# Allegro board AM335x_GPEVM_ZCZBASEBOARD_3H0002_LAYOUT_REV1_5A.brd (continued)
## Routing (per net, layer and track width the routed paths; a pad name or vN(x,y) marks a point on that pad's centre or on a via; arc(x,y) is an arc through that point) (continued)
AM335X_MCASP0_AXR0: length 145.4
  TOP w0.102: v2(81,87.4) U2.D12
  TOP w0.121: 29.5,124.75 34.58,124.75 38.91,120.43 68.04,120.43 68.36,120.75 73.13,120.75 74.92,122.55 78.23,122.55 78.53,122.85 v1(79.03,122.85) ; R451.1 87.54,155.57 86.05,154.08 85.55,154.08 85.31,153.84 84.69,153.84 84.45,154.08 81.63,154.08 81.56,154.15 v1(78.08,154.15)
  LY4 w0.133: v1(79.03,122.85) 71,114.82 71,111.47 70.01,110.48 70.01,99.61 v1(69.32,98.91)
  BOTTOM w0.102: v2(81,87.4) 81,87.6 80.58,88.02 80.58,88.4 80.36,88.62 80.04,88.62 80.04,88.62 79.92,88.62 79.79,88.75 79.79,89.19 79.6,89.38 79.03,89.38 78.94,89.47 77.05,89.47
  BOTTOM w0.121: v1(78.08,154.15) 77.53,153.61 77.53,147.97 77.33,147.76 77.33,136.97 78.03,136.27 78.03,135.03 77.91,134.92 77.91,134.1 78.97,133.04 78.97,125.25 79.26,124.96 79.26,123.56 79.61,123.21 79.61,123.2 79.64,123.17 79.65,123.17 79.92,122.9 R203.1 v1(79.03,122.85) ; 77.05,89.47 73.56,89.47 70.74,92.29 70.74,93.15 69.36,94.53 69.36,95.2 68.97,95.6 68.97,96.08 68.97,96.1 68.97,97.93 69.32,98.27 v1(69.32,98.91)
AM335X_MCASP0_AXR1: length 110.1
  TOP w0.102: v2(80.2,88.2) U2.D13
  TOP w0.121: R348.1 50.02,128.11 39.86,128.11 v1(38.52,129.45)
  LY3 w0.133: v1(33.79,87.41) 34.11,87.73 55.15,87.73 57.73,90.3 62.36,90.3 65.32,93.26 v1(70.01,93.26)
  BOTTOM w0.102: v2(80.2,88.2) 80.2,88.21 80,88.42 79.84,88.42 79.63,88.62 78.97,88.62 78.61,88.98 77.1,88.98
  BOTTOM w0.121: v1(38.52,129.45) 38.04,128.97 37.4,128.97 35.85,127.42 35.85,113.5 34.4,112.05 34.4,107.42 34.41,107.41 34.41,107.04 34.4,107.03 34.4,98.49 33.46,97.55 33.46,87.74 v1(33.79,87.41) ; v1(70.01,93.26) 70.01,93.18 69.84,93 69.84,92.48 70.18,92.14 70.19,92.14 73.35,88.98 77.1,88.98
AM335X_MCASP0_FSR: length 29.9
  TOP w0.102: v2(79.4,88.2) U2.C13
  TOP w0.121: R336.1 70.65,104.3 v1(69.44,104.3)
  BOTTOM w0.102: 77.1,88.73 77.81,88.73 78.35,88.2 v2(79.4,88.2)
  BOTTOM w0.121: v1(69.44,104.3) 69.19,104.05 69.19,100.88 68.76,100.45 68.76,99.73 68.87,99.61 68.87,98.34 68.72,98.18 68.72,96.11 68.72,96.09 68.72,95.5 68.93,95.29 68.93,95.26 69.12,95.08 69.12,94.49 68.77,94.14 68.77,92.29 69.13,91.93 70.04,91.93 70.3,91.67 70.3,91.25 71.48,90.07 71.91,90.07 73.25,88.73 77.1,88.73
AM335X_MCASP0_FSX: length 58.8
  TOP w0.102: U2.B13 78.63,88.18 77.63,88.18 77.1,88.7
  TOP w0.121: R335.1 v1(82.46,121.83) ; 77.1,88.7 76.64,89.17 75.75,89.17 74.78,90.14 69.88,90.14 v1(69.69,90.34) ; v1(67.16,117.51) 67.89,118.25 74.5,118.25 75.98,119.73 v1(81,119.73)
  BOTTOM w0.121: v1(81,119.73) 81.32,120.05 81.32,120.69 v1(82.46,121.83) R199.1 ; v1(69.69,90.34) 69.22,90.34 68.52,91.04 68.52,94.25 68.87,94.6 68.87,94.97 68.44,95.4 68.47,96.12 68.47,98.46 68.51,98.5 68.51,100.95 68.94,101.38 68.94,104.15 68.94,104.16 68.94,110.86 68.8,111 68.8,112.56 68.66,112.71 68.66,115.06 67.16,116.56 v1(67.16,117.51)
AM335X_MMC2_CLK: length 2.3
  TOP w0.121: U28.9 20.46,108.87 20,109.33 19.49,109.33 19.37,109.21 19.37,108.9 R459.1
AM335X_MMC2_CMD: length 2.3
  TOP w0.121: U28.4 22.77,111.39 22.39,111.77 22.39,112.18 R460.1
AM335X_MMC2_D0: length 126.3
  TOP w0.121: U28.6 21.77,110.89 20.42,112.24 20.42,113.95 v1(20.81,114.34)
  LY3 w0.133: v1(20.81,114.34) 21.24,114.76 24.25,114.76 24.4,114.62 25.18,114.62 25.48,114.32 34.94,114.32 39.81,119.18 51.58,119.18 53.07,120.67 68.93,120.67 69.06,120.55 69.06,119.7 69.18,119.58 70.47,119.58 70.6,119.7 70.6,120.55 70.73,120.67 71.61,120.67 71.74,120.55 71.74,119.7 71.87,119.58 73.04,119.58 73.16,119.7 73.16,120.55 73.29,120.67 74.05,120.67 75.27,121.9 81.73,121.9 82.49,121.14 105.55,121.14 105.62,121.07 105.74,121.07 v1(106.23,120.58)
  BOTTOM w0.121: R456.1 104.55,95.35 105.58,95.35 106.7,96.48 106.7,117.09 107.41,117.79 107.41,119.99 106.82,120.58 v1(106.23,120.58)
AM335X_MMC2_D1: length 126.6
  TOP w0.121: v1(20.05,114.36) 20.05,112.05 21.05,111.05 U28.7
  LY3 w0.133: v1(107.74,120.28) 107.73,120.28 106.61,121.4 83.52,121.4 82.65,122.28 74.92,122.28 74.54,121.9 70.88,121.9 70.58,121.6 70.57,121.6 70.27,121.3 68.39,121.3 68.11,121.58 67.54,121.58 66.9,120.93 52.96,120.93 51.47,119.44 39.7,119.44 34.84,114.58 25.59,114.58 25.25,114.92 24.5,114.92 24.33,115.1 20.79,115.1 v1(20.05,114.36)
  BOTTOM w0.121: v1(107.74,120.28) 107.74,117.77 106.95,116.99 106.95,96.38 105.68,95.11 103.53,95.11 R457.1
AM335X_MMC2_D2: length 126.1
  TOP w0.121: v1(25.06,114.08) 24.93,113.96 24.93,111.67 24.27,111.02 U28.1
  LY3 w0.133: v1(106.96,119.8) 106.64,120.13 105.98,120.13 105.22,120.88 87.99,120.88 87.81,120.7 82.48,120.7 81.72,121.46 75.39,121.46 73.24,119.32 63.77,119.32 63.64,119.44 63.64,119.72 63.77,119.85 68.67,119.85 68.79,119.98 68.79,120.29 68.67,120.41 53.18,120.41 51.69,118.92 39.91,118.92 34.87,113.88 25.31,113.88 25.11,114.08 v1(25.06,114.08)
  BOTTOM w0.121: v1(106.96,119.8) 107.16,119.61 107.16,117.89 106.46,117.19 106.46,97 R458.1
AM335X_MMC2_D3: length 2.2
  TOP w0.121: R491.1 23.91,112.48 23.27,111.84 U28.3
AM335X_MMC_CLK: length 64.9
  TOP w0.102: 82.65,92.9 82.65,91.35 U2.G17
  TOP w0.121: 82.65,92.9 82.65,93.59 83.16,94.1 83.16,94.12 83.21,94.16 83.21,95.53 82.82,95.92 v1(82.82,96)
  BOTTOM w0.121: v1(82.82,96) 82.82,96.31 83.22,96.71 83.22,97.24 83.22,97.45 83.07,97.6 83.07,98.2 82.89,98.38 81.73,99.54 81.73,100.81 81.4,101.14 81.4,106.03 81.39,106.04 80.76,106.67 80.76,118.49 80.75,118.49 80.75,118.7 80.76,118.76 82.01,120.02 82.01,120.49 83.56,122.04 83.56,129.67 83.43,129.79 82.81,129.79 82.69,129.91 82.69,130.15 82.81,130.27 83.43,130.27 83.56,130.39 83.56,130.63 83.43,130.75 82.81,130.75 82.69,130.88 82.69,131.12 82.81,131.24 83.43,131.24 83.56,131.36 83.56,131.6 83.43,131.72 82.81,131.72 82.69,131.84 82.69,132.08 82.81,132.2 83.43,132.2 83.56,132.32 83.56,132.56 83.43,132.69 82.81,132.69 82.69,132.81 82.69,133.05 82.81,133.17 83.43,133.17 83.56,133.29 83.56,133.53 83.43,133.65 82.81,133.65 82.69,133.77 82.69,134.01 82.81,134.13 83.43,134.13 83.56,134.25 83.56,134.5 83.43,134.62 82.81,134.62 82.69,134.74 82.69,134.98 82.81,135.1 83.43,135.1 83.56,135.22 83.56,135.47 82.71,136.31 82.71,142.66 R197.2
AM335X_MMC_CMD: length 78.7
  TOP w0.102: U2.G18 83,92.9
  TOP w0.121: v1(83.1,93.41) 83,93.31 83,92.9 ; v1(85.86,143.52) 85.42,143.52 85.27,143.67 82.52,143.67 82.39,143.55 v1(81.95,143.55)
  BOTTOM w0.121: R200.2 v1(81.95,143.55) ; v1(83.1,93.41) 83.1,93.41 83.58,93.89 83.88,93.89 85.79,95.8 85.79,102 85.6,102.19 85.6,102.56 86.38,103.34 86.39,103.34 86.39,114.46 87.03,115.11 87.03,116 87.04,116.01 87.04,116.37 87.03,116.38 87.03,122.46 88.76,124.19 88.76,126.34 88.88,126.46 90.09,126.46 90.21,126.58 90.21,126.82 90.09,126.94 88.88,126.94 88.76,127.06 88.76,127.3 88.88,127.42 90.09,127.42 90.21,127.55 90.21,127.79 90.09,127.91 88.88,127.91 88.76,128.03 88.76,128.27 88.88,128.39 90.09,128.39 90.21,128.51 90.21,128.75 90.09,128.87 88.88,128.87 88.76,128.99 88.76,129.23 88.88,129.35 90.09,129.35 90.21,129.48 90.21,129.72 90.09,129.84 88.88,129.84 88.76,129.96 88.76,130.2 88.88,130.32 90.09,130.32 90.21,130.44 90.21,130.68 90.09,130.8 88.88,130.8 88.76,130.92 88.76,131.16 88.88,131.29 90.09,131.29 90.21,131.41 90.21,131.65 90.09,131.77 88.88,131.77 88.76,131.89 88.76,132.13 88.88,132.25 90.09,132.25 90.21,132.37 90.21,132.61 90.09,132.73 88.88,132.73 87.39,134.23 87.39,140.19 85.86,141.72 v1(85.86,143.52)
AM335X_MMC_D0: length 60.5
  TOP w0.102: v2(82.6,90.6) U2.G16
  BOTTOM w0.102: 82.6,93.8 v2(82.6,90.6)
  BOTTOM w0.121: 82.6,93.8 82.05,94.34 82.05,95.92 82.97,96.84 82.97,97.34 82.83,97.49 82.83,98.1 81.48,99.44 81.48,99.64 81.48,100.71 81.15,101.04 81.15,101.62 81.15,105.92 81.14,105.94 80.5,106.58 80.5,107.03 80.5,121.14 81.77,122.41 81.77,124.85 81.51,125.12 81.51,131.66 81.63,131.78 82.26,131.78 82.38,131.9 82.38,132.14 82.26,132.26 81.63,132.26 81.51,132.38 81.51,132.63 81.63,132.75 82.26,132.75 82.38,132.87 82.38,133.11 82.26,133.23 81.63,133.23 81.26,133.6 81.26,135.22 80.24,136.24 80.24,140.69 80.36,140.81 80.36,142.83 79.77,143.42 79.18,143.42 79.15,143.45 R399.2
AM335X_MMC_D1: length 72.8
  TOP w0.102: v2(82.6,89.8) U2.G15
  TOP w0.121: v1(71.79,143.45) 72.39,142.85 80.1,142.85 80.16,142.79 80.94,142.79 82.37,141.35 83.31,141.35 83.73,141.77 84.41,141.77 84.44,141.74 v1(84.82,141.74)
  LY4 w0.133: v1(86.04,102.37) 83.63,104.79 83.63,106.26 81.76,108.13 81.76,113.91 82.16,114.31 v1(82.16,116.12)
  BOTTOM w0.102: v2(82.6,89.8) 83.02,90.22 83.02,92.59 83.32,92.9
  BOTTOM w0.121: R400.2 v1(71.79,143.45) ; v1(82.16,116.12) 82.16,117.74 83.58,119.16 83.58,120.81 84.75,121.98 84.75,123.56 85.95,124.76 85.95,128.75 84.93,129.78 84.93,140.11 84.82,140.21 v1(84.82,141.74) ; v1(86.04,102.37) 86.04,95.54 84.34,93.84 84.26,93.84 83.32,92.9
AM335X_MMC_D2: length 89.5
  TOP w0.102: 82.4,93.1 82.4,92 U2.F18
  TOP w0.121: v1(69.23,143.45) 67.14,143.45 67.02,143.32 67.02,142.53 67.14,142.4 67.23,142.4 67.35,142.28 67.35,141.64 67.47,141.52 67.71,141.52 67.83,141.64 67.83,142.28 67.95,142.4 68.19,142.4 68.32,142.28 68.32,141.64 68.44,141.52 68.68,141.52 68.8,141.64 68.8,142.28 68.92,142.4 69.16,142.4 69.28,142.28 69.28,141.64 69.4,141.52 69.64,141.52 69.76,141.64 69.76,142.28 69.88,142.4 70.37,142.4 70.49,142.28 70.49,141.57 70.61,141.45 70.85,141.45 70.97,141.57 70.97,142.28 71.1,142.4 71.34,142.4 71.46,142.28 71.46,141.57 71.58,141.45 71.82,141.45 71.94,141.57 71.94,142.28 72.06,142.4 72.3,142.4 72.42,142.28 72.42,141.57 72.54,141.45 72.78,141.45 72.9,141.57 72.9,142.28 73.03,142.4 73.27,142.4 73.39,142.28 73.39,141.57 73.51,141.45 73.75,141.45 73.87,141.57 73.87,142.28 73.99,142.4 74.23,142.4 74.35,142.28 74.35,141.57 74.47,141.45 74.71,141.45 74.84,141.57 74.84,142.28 74.96,142.4 75.2,142.4 75.32,142.28 75.32,141.57 75.44,141.45 75.68,141.45 75.8,141.57 75.8,142.28 75.92,142.4 76.16,142.4 76.28,142.28 76.28,141.57 76.4,141.45 76.65,141.45 76.77,141.57 76.77,142.28 76.89,142.4 77.13,142.4 77.25,142.28 77.25,141.57 77.37,141.45 77.61,141.45 77.73,141.57 77.73,142.28 77.85,142.4 78.09,142.4 78.21,142.28 78.21,141.57 78.33,141.45 78.58,141.45 78.7,141.57 78.7,142.28 78.82,142.4 v1(79.92,142.4) ; 82.4,93.1 82.4,94.66 82.33,94.74 82.33,96.38 82.42,96.47 v1(82.42,97.09)
  BOTTOM w0.121: v1(82.42,97.09) 81.44,98.06 81.44,98.71 80.87,99.28 80.87,100.62 80.64,100.85 80.64,105.73 80.01,106.37 80.01,106.83 80.01,107.3 79.38,107.93 79.38,120.78 80.56,121.96 80.56,124.75 81.02,125.21 81.02,129.75 80.37,130.4 80.37,134.77 v1(80.31,134.83) 80.31,135.28 79.67,135.92 79.67,141.25 79.41,141.51 79.41,141.9 v1(79.92,142.4) ; R215.2 v1(69.23,143.45)
AM335X_MMC_D3: length 86.9
  TOP w0.102: 81.89,91.97 81.89,91.96 81.87,91.94 81.87,91.31 82.18,91 U2.F17
  TOP w0.121: v1(82.38,97.79) 82.18,97.59 82.18,97.48 81.97,97.27 81.97,94.74 82.16,94.56 82.16,92.24 81.89,91.97 ; v1(79.92,141.62) 79.83,141.62 79.41,141.2 79.13,141.2 79.01,141.08 79.01,140.93 78.89,140.81 78.65,140.81 78.53,140.93 78.53,141.08 78.41,141.2 78.16,141.2 78.04,141.08 78.04,140.93 77.92,140.81 77.68,140.81 77.56,140.93 77.56,141.08 77.44,141.2 77.2,141.2 77.08,141.08 77.08,140.93 76.96,140.81 76.72,140.81 76.6,140.93 76.6,141.08 76.48,141.2 76.23,141.2 76.11,141.08 76.11,140.93 75.99,140.81 75.75,140.81 75.63,140.93 75.63,141.08 75.51,141.2 75.27,141.2 75.15,141.08 75.15,140.93 75.03,140.81 74.79,140.81 74.67,140.93 74.67,141.08 74.55,141.2 74.3,141.2 74.18,141.08 74.18,140.93 74.06,140.81 73.82,140.81 73.7,140.93 73.7,141.08 73.58,141.2 73.34,141.2 73.22,141.08 73.22,140.93 73.1,140.81 72.86,140.81 72.74,140.93 72.74,141.08 72.61,141.2 72.37,141.2 72.25,141.08 72.25,140.93 72.13,140.81 71.89,140.81 71.77,140.93 71.77,141.08 71.65,141.2 71.41,141.2 71.29,141.08 71.29,140.93 71.17,140.81 70.93,140.81 70.81,140.93 70.81,141.08 70.68,141.2 70.44,141.2 70.32,141.08 70.32,140.93 70.2,140.81 69.96,140.81 69.84,140.93 69.84,141.08 69.72,141.2 69.48,141.2 69.36,141.08 69.36,140.93 69.24,140.81 69,140.81 68.87,140.93 68.87,141.08 68.75,141.2 67.05,141.2 66.36,141.9 v1(66.36,142.94)
  BOTTOM w0.121: v1(82.38,97.79) 81.88,98.3 81.88,98.66 81.24,99.3 81.24,99.34 81.24,100.6 81.12,100.72 80.89,100.95 80.89,105.84 80.25,106.47 80.25,106.93 80.25,107.4 79.63,108.03 79.63,109.06 79.75,109.18 80.13,109.18 80.25,109.3 80.25,109.54 80.13,109.66 79.75,109.66 79.63,109.78 79.63,110.03 79.75,110.15 80.13,110.15 80.25,110.27 80.25,110.51 80.13,110.63 79.75,110.63 79.63,110.75 79.63,110.99 79.75,111.11 80.13,111.11 80.25,111.23 80.25,111.47 80.13,111.59 79.75,111.59 79.63,111.71 79.63,111.96 79.75,112.08 80.13,112.08 80.25,112.2 80.25,112.44 80.13,112.56 79.75,112.56 79.63,112.68 79.63,112.92 79.75,113.04 80.13,113.04 80.25,113.16 80.25,113.4 80.13,113.52 79.75,113.52 79.63,113.64 79.63,113.89 79.75,114.01 80.13,114.01 80.25,114.13 80.25,114.37 80.13,114.49 79.75,114.49 79.63,114.61 79.63,114.85 79.75,114.97 80.13,114.97 80.25,115.09 80.25,115.33 80.13,115.45 79.75,115.45 79.63,115.58 79.63,115.82 79.75,115.94 80.13,115.94 80.25,116.06 80.25,116.3 80.13,116.42 79.75,116.42 79.63,116.54 79.63,116.78 79.75,116.9 80.13,116.9 80.25,117.02 80.25,117.26 80.13,117.39 79.75,117.39 79.63,117.51 79.63,117.75 79.75,117.87 80.13,117.87 80.25,117.99 80.25,118.23 80.13,118.35 79.75,118.35 79.63,118.47 79.63,118.71 79.75,118.83 80.13,118.83 80.25,118.95 80.25,119.19 80.13,119.32 79.75,119.32 79.63,119.44 79.63,119.68 79.75,119.8 80.13,119.8 80.25,119.92 80.25,120.16 80.13,120.28 79.75,120.28 79.63,120.4 79.63,120.65 81.26,122.28 81.26,130.02 80.62,130.67 80.62,134.45 80.81,134.65 80.81,135.16 79.99,135.98 79.99,141.55 v1(79.92,141.62) ; v1(66.36,142.94) 66.36,143.29 66.46,143.39 R396.2
AM335X_OSC0_IN: length 20.2
  TOP w0.102: 94.38,85.1 92.78,85.1 92.47,85.4 U2.V10
  TOP w0.121: Y2.3 106.97,78.65 106.97,79.92 106.74,80.15 C4.1 101.41,80.76 101.41,80.94 R7.2 99.85,82.49 99.85,84.18 98.45,85.58 94.86,85.58 94.38,85.1
AM335X_OSC0_OUT: length 11.4
  TOP w0.121: U2.U11 91.43,86.63 91.91,86.63 92.04,86.76 92.95,86.76 93.37,87.17 94.36,87.17 95.32,86.21 98.78,86.21 100.06,84.93 100.52,84.93 R8.1
AM335X_OSC1_IN: length 15.2
  TOP w0.102: 77.74,81.97 77.97,81.97 U2.A6
  TOP w0.121: Y1.4 64.93,79.11 65.71,79.9 65.86,79.9 66.71,80.74 C2.2 67.42,80.77 67.45,80.8 68.46,80.8 68.83,80.43 71.12,80.43 71.35,80.66 72.66,80.66 73.32,81.32 75.69,81.32 76.01,81.64 76.42,81.64 76.43,81.63 77.2,81.63 77.22,81.6 77.36,81.6 77.74,81.97
AM335X_OSC1_OUT: length 8.5
  TOP w0.102: 77.1,80.89 77.91,80.89 U2.A4
  TOP w0.121: 77.1,80.89 76.32,80.89 75.34,79.91 71.66,79.91 71.27,79.53 70.95,79.53 70.84,79.41 R5.1
AM335X_PORZ: length 31.8
  TOP w0.102: U2.B15 79,89.41 78.54,89.87 78.06,89.87
  TOP w0.121: 78.06,89.87 77.33,89.87 76.99,90.22 76.67,90.22 v1(76.36,90.53) ; v1(70.62,100.19) 70.62,99.58 70.52,99.48 R9.2 69.69,99.8 69.69,100.05 69.69,100.05 69.69,100.1 69.4,100.39 68.57,100.39 67.36,99.19 65.02,99.19 64.16,98.34 63.76,98.34 63.28,98.82 61.96,98.82 v1(61.81,98.97)
  LY4 w0.133: v1(61.81,98.97) 62.13,99.29 62.29,99.29 63.16,100.16 63.16,101.12 62.78,101.51 v1(62.78,102.07)
  BOTTOM w0.121: v1(70.62,100.19) 71.14,100.19 71.47,99.86 71.47,98.59 71.86,98.21 72.55,98.21 73.19,97.57 73.19,94.22 74.33,93.08 74.33,92.37 75.73,90.97 75.92,90.97 v1(76.36,90.53) ; R2.1 v1(62.78,102.07)
AM335X_RTC_PORZ: length 50
  TOP w0.102: 76.32,81.39 77.49,81.39 77.86,81.76 78.65,81.76 79,81.41 U2.B5
  TOP w0.121: 76.32,81.39 76.12,81.39 75.79,81.06 73.44,81.06 72.79,80.41 71.45,80.41 71.22,80.17 68.73,80.17 68.55,80.36 v1(68.11,80.36) ; U1.4 53.7,103.05 53.5,102.85 53.5,99.88 54.06,99.33 56.43,99.33 57.11,98.64 v1(59.6,98.64)
  LY3 w0.133: v1(61.93,80.68) 61.93,80.64 62.21,80.36 v1(68.11,80.36)
  BOTTOM w0.121: v1(61.93,80.68) 61.71,80.9 61.71,82.64 61.08,83.28 61.08,86.18 60.79,86.47 60.36,86.91 60.36,87.52 60.36,87.52 60.36,87.91 59.22,89.05 59.22,92.18 59.3,92.27 59.3,93.56 59.3,93.56 59.3,94.48 60.08,95.26 60.08,98.16 v1(59.6,98.64) 60.54,99.58 60.77,99.58 R4.2
AM335X_SPI0_CS0: length 107
  TOP w0.102: v2(77.3,90.46) 77.48,90.28 78.12,90.28 U2.A16
  TOP w0.121: R313.2 131.36,95.29 v1(131.86,95.8)
  LY3 w0.133: v1(119.82,108.7) 119.52,109 119.52,109.97 119.1,110.39 118.72,110.39 118.63,110.3 108.98,110.3 108.04,111.24 101.08,111.24 100.27,112.04 90.57,112.04 89.6,113.01 87.59,113.01 87.34,113.26 86.97,113.26 86.68,112.97 77.84,112.97 77.3,112.43 v1(69.86,112.43)
  BOTTOM w0.102: 77.1,90.44 77.13,90.46 v2(77.3,90.46)
  BOTTOM w0.121: v1(119.82,108.7) 120.36,108.7 120.63,108.43 120.63,97.56 122.83,95.36 130.41,95.36 130.85,95.8 v1(131.86,95.8) ; 77.1,90.44 76.75,90.08 75.73,90.08 73.83,91.98 73.83,92.82 72.69,93.96 72.69,94 72.68,94.02 72.68,95.67 R552.1 72.94,96.94 72.94,97.48 72.51,97.91 71.81,97.91 71.09,98.62 71.09,99.42 70.76,99.75 70.44,99.75 70.18,100.01 70.18,100.6 70.01,100.77 70.01,103.48 70.38,103.85 70.38,105.79 69.69,106.48 69.69,111.31 69.86,111.49 v1(69.86,112.43)
AM335X_SPI0_CS1: length 10.4
  TOP w0.102: v2(79.4,89.8) U2.C15
  TOP w0.121: v1(73.01,90.83) 73.02,90.84 73.02,91.16 72.61,91.56 72.61,91.82 72.3,92.13 R380.2 72.29,92.19 71.33,92.19 R208.1
  BOTTOM w0.102: v2(79.4,89.8) 79.32,89.72 77.1,89.72
  BOTTOM w0.121: v1(73.01,90.83) 73.01,90.44 73.73,89.72 77.1,89.72
AM335X_SPI0_D0: length 106.7
  TOP w0.102: U2.B17 78.65,91.35 77.1,91.35
  TOP w0.121: v1(74.36,133.26) 74.79,133.26 74.92,133.39 74.92,133.64 75.04,133.77 76.36,133.77 76.48,133.65 76.48,132.9 76.6,132.78 76.84,132.78 76.96,132.9 76.96,133.65 77.08,133.77 77.33,133.77 77.45,133.65 77.45,132.9 77.57,132.78 77.81,132.78 77.93,132.9 77.93,133.65 78.05,133.77 79.09,133.77 79.22,133.64 79.22,132.56 79.09,132.43 74.27,132.43 74.08,132.24 74.08,132.05 74.27,131.86 80.02,131.86 81.39,133.23 81.39,133.51 81.26,133.64 79.79,133.64 79.67,133.77 R436.1 ; 77.1,91.35 76.82,91.63 75.01,91.63 74.33,92.3 74.33,94.69 v1(73.88,95.13)
  BOTTOM w0.121: v1(73.88,95.13) 73.88,96.93 74.52,97.57 74.52,97.84 76.1,99.42 76.1,103.29 75.98,103.42 75.98,106.8 76.1,106.92 77.07,106.92 77.19,107.04 77.19,107.28 77.07,107.41 76.1,107.41 75.98,107.53 75.98,107.77 76.1,107.89 77.07,107.89 77.19,108.01 77.19,108.25 77.07,108.37 76.1,108.37 75.98,108.49 75.98,108.93 76.1,109.05 76.97,109.05 77.09,109.17 77.09,109.41 76.97,109.53 76.1,109.53 75.98,109.65 75.98,109.9 76.1,110.02 76.97,110.02 77.09,110.14 77.09,110.38 76.97,110.5 76.1,110.5 75.98,110.62 75.98,110.86 76.1,110.98 76.97,110.98 77.09,111.1 77.09,111.34 76.97,111.46 76.1,111.46 75.98,111.58 75.98,111.83 76.1,111.95 76.97,111.95 77.09,112.07 77.09,112.31 76.97,112.43 76.1,112.43 75.98,112.55 75.98,112.79 76.1,112.91 76.97,112.91 77.09,113.03 77.09,113.27 76.97,113.39 76.1,113.39 75.98,113.52 75.98,113.76 76.1,113.88 76.97,113.88 77.09,114 77.09,114.24 76.97,114.36 76.1,114.36 75.98,114.48 75.98,114.72 76.1,114.84 76.97,114.84 77.09,114.96 77.09,115.2 76.97,115.32 76.1,115.32 75.98,115.45 75.98,115.69 76.1,115.81 76.97,115.81 77.09,115.93 77.09,116.17 76.97,116.29 76.1,116.29 75.98,116.41 75.98,116.65 76.1,116.77 76.97,116.77 77.09,116.89 77.09,117.13 76.97,117.26 76.1,117.26 75.98,117.38 75.98,118.23 76.1,118.35 76.75,118.35 76.87,118.47 76.87,118.71 76.75,118.83 76.1,118.83 75.98,118.95 75.98,119.84 75.29,120.53 75.29,120.63 73.5,122.42 73.5,129.65 73.37,129.77 72.68,129.77 72.55,129.9 72.55,130.55 72.68,130.67 74.6,130.67 74.72,130.79 74.72,131.04 74.6,131.16 71.89,131.16 71.77,131.28 71.77,131.51 71.89,131.64 74.6,131.64 74.72,131.76 74.72,132 74.6,132.12 73.93,132.12 73.81,132.24 73.81,132.71 v1(74.36,133.26)
AM335X_SPI0_D1: length 15
  TOP w0.102: U2.B16 78.61,90.59 78.1,90.59 77.83,90.85
  TOP w0.121: R177.1 71.54,93.76 71.99,93.32 72.37,93.32 v1(72.81,92.87) 73.06,92.62 73.32,92.62 74.8,91.13 76.62,91.13 76.89,90.85 77.83,90.85
  BOTTOM w0.121: v1(72.81,92.87) 71.72,93.96 71.72,95.34 71.03,96.03 R553.1
AM335X_SPI0_SCLK: length 8
  TOP w0.102: 78.02,91 U2.A17
  TOP w0.121: 78.02,91 77.92,91.1 77,91.1 76.72,91.38 74.9,91.38 73.25,93.04 73.25,93.06 72.99,93.32 72.97,93.32 72.66,93.63 72.19,93.63 72.07,93.75 72.06,93.75 R201.1
AM335X_UART0_CTSN: length 13.6
  TOP w0.102: 81.91,92.9 81.91,92.31 U2.E18
  TOP w0.121: 81.91,92.9 81.91,94.45 81.73,94.64 81.73,97.48 81.94,97.7 81.94,99.74 79.29,102.4 79.29,103.16 R61.2
AM335X_UART0_RTSN: length 10.8
  TOP w0.102: U2.E17 81.4,91.01 81.06,91.35 81.06,91.99 81.65,92.57 81.65,92.9
  TOP w0.121: R362.2 80.17,99.23 81.34,99.23 81.69,98.87 81.69,97.87 81.66,97.83 81.66,97.83 81.48,97.65 81.48,97.48 81.48,94.53 81.65,94.36 81.65,92.9
AM335X_UART0_RXD: length 105
  TOP w0.102: v2(81,89.8) U2.E15
  TOP w0.121: v1(52.23,63.41) R249.2 ; v1(78.64,105.46) 78.02,104.84 77.81,104.84 77.4,104.44 77.4,103.47 78.4,102.48 78.4,100.2 78.15,99.95 78.15,99.52 78.57,99.1 79.54,99.1 80.17,98.46 R363.2 80.2,98.08 80.62,97.66 80.91,97.66 81.23,97.34 81.23,97.17 81.23,94.53 81.18,94.48 v1(81.18,94.04)
  LY3 w0.133: v1(51.14,107.12) 51.48,107.46 51.48,107.59 51.74,107.85 51.87,107.85 51.9,107.89 53.17,107.89 54.52,106.54 77.56,106.54 v1(78.64,105.46)
  BOTTOM w0.102: v2(81,89.8) 81,89.83 80.58,90.24 80.58,90.97
  BOTTOM w0.121: v1(51.14,107.12) 47.43,107.12 44.84,104.53 44.84,103.38 44.81,103.35 44.81,98.78 44.64,98.61 44.64,94.02 45.12,93.53 45.12,80.81 44.35,80.04 43.04,78.72 43.04,71.95 48.02,66.97 51.22,66.97 52.23,65.95 v1(52.23,63.41) ; 80.58,90.97 80.54,91.01 80.54,93.45 81.14,94.04 v1(81.18,94.04)
AM335X_UART0_TXD: length 15.9
  TOP w0.102: v2(81,90.6) U2.E16
  TOP w0.121: v1(79,96.27) 78.7,96.57 73.31,96.57 R361.2
  BOTTOM w0.102: 80.79,92.9 80.79,92.36 81,92.15 v2(81,90.6)
  BOTTOM w0.121: v1(79,96.27) 79.05,96.33 80.76,96.33 81.62,95.46 81.62,93.79 81.42,93.59 81.06,93.59 80.79,93.31 80.79,92.9
AM335X_UART1_CTSN: length 17.9
  TOP w0.102: U2.D18 80.74,91.94
  TOP w0.121: R357.1 75.86,103.54 76.56,103.54 v1(76.56,103.54) ; 80.74,91.94 80.74,94.51 80.98,94.75 80.98,96.53 80.79,96.73 v1(80.79,96.99)
  BOTTOM w0.121: v1(76.56,103.54) 78.12,103.54 79.46,102.2 79.46,101.15 78.93,100.62 78.9,100.62 79.45,100.08 79.45,96.83 79.71,96.57 80.37,96.57 80.78,96.99 v1(80.79,96.99)
AM335X_UART1_RTSN: length 17.7
  TOP w0.102: 80.24,91.92 80.24,91.35 80.59,91 U2.D17
  TOP w0.121: 80.24,91.92 80.49,92.17 80.49,94.69 80.74,94.93 80.74,96.41 80.34,96.81 80.34,97.3 80.14,97.51 77.57,97.51 76.74,98.34 76.74,99.99 R443.1 76.75,101 76.75,102.17 v1(76.54,102.37)
  BOTTOM w0.121: v1(76.54,102.37) 76.54,102.35 76.9,101.99 76.9,101.33 77.61,100.62 77.76,100.62
AM335X_UART1_RXD: length 15.5
  TOP w0.102: v2(80.2,90.6) U2.D16
  TOP w0.121: v1(79.88,95.88) 79.88,96.39 79.01,97.26 77.47,97.26 76.36,98.37 76.36,98.59 75.48,99.48 74.59,99.48 74.34,99.23 73.19,99.23 R356.1
  BOTTOM w0.102: 80.29,93.51 80.29,91.06 80.2,90.97 v2(80.2,90.6)
  BOTTOM w0.121: v1(79.88,95.88) 80.29,95.47 80.29,93.51
AM335X_UART1_TXD: length 12.7
  TOP w0.102: v2(80.2,89.8) U2.D15
  TOP w0.121: R91.2 75.34,96.81 79.11,96.81 79.44,96.48 79.44,95.7 79.85,95.29 v1(79.85,95.16)
  BOTTOM w0.102: v2(80.2,89.8) 79.98,90.02 79.98,90.04 79.78,90.25 79.78,90.43
  BOTTOM w0.121: 79.78,90.43 79.79,90.44 79.79,90.84 79.99,91.04 79.99,91.06 80.05,91.12 80.05,94.49 79.85,94.68 v1(79.85,95.16)
AM335X_USB0_CE: length 14.1
  TOP w0.102: v2(87.4,89.8) U2.M15
  TOP w0.121: v1(93.67,99.26) 93.64,99.23 93.64,99.09 93.14,98.59 TP23.1
  LY3 w0.133: v1(93.67,99.26) 93.25,98.84 92.24,98.84 89.57,96.18 89.57,95.13 87.86,93.42 87.86,90.82 87.8,90.76 87.8,90.46 87.8,90.46 87.8,90.21 87.4,89.81 v2(87.4,89.8)
AM335X_USB0_DRVVBUS: length 106.2
  TOP w0.102: U2.F16 v2(81.8,90.6)
  TOP w0.121: v1(138.42,144.6) 137.87,145.15 U22.4
  LY3 w0.133: v1(138.42,144.6) 137.36,143.55 121.45,143.55 118.66,140.75 101.51,140.75 94.59,133.83 v1(86.4,133.83)
  LY4 w0.133: v2(81.8,90.6) 81.8,91.45 80.97,92.29 80.96,92.29 80.73,92.52 80.73,92.52 80.49,92.77 80.49,94.33 81.33,95.18 81.33,97.27 81.26,97.34 81.26,98.24 81.33,98.31 81.33,117.58 82.49,118.73 83.07,118.73 83.98,119.65 83.98,129.51 85.06,130.59 85.06,132.69 86.21,133.83 v1(86.4,133.83)
  BOTTOM w0.121: v1(138.42,144.6) 137.35,144.6 R383.1
AM335X_USB0_VBUS: length 17.6
  TOP w0.254: v2(89,89.8) U2.P15 ; R563.2 96.3,96.24 D9.1
  TOP w0.508: v1(94.84,97.05) 95.99,97.05 R563.2
  LY3 w0.127: 89.01,91.27 89.41,90.88 89.41,90.21 v2(89,89.8)
  LY3 w0.133: 89.01,91.27 88.6,90.86 88.6,90.2 v2(89,89.8)
  LY3 w0.508: 89.01,91.27 89.01,93.79 90,94.78 90.64,94.78 91.99,96.13 91.99,97.01 92.47,97.5 94.39,97.5 v1(94.84,97.05)
AM335X_USB1_CE: length 6.2
  TOP w0.102: 88.6,92.9 U2.P18
  TOP w0.121: 88.6,92.9 88.6,93.55 89.56,94.52 90.45,94.52 91.35,95.41 TP36.1
AM335X_USB1_DRVVBUS: length 133.6
  TOP w0.102: U2.F15 v2(81.8,89.8)
  TOP w0.121: U29.4 v1(146.58,144.83)
  LY3 w0.133: v1(143.36,132.94) 142.53,133.77 142.53,139.48 138.85,143.17 121.7,143.17 118.91,140.37 101.76,140.37 94.65,133.26 86.21,133.26 v1(85.57,133.9)
  LY4 w0.133: v1(85.57,133.9) 83.54,131.86 83.54,121.57 82.49,120.53 82.49,119.49 80.56,117.55 80.56,105.07 79.98,104.5 79.98,98.78 80.34,98.43 80.34,94.88 79.98,94.53 79.98,92.9 81.41,91.48 81.41,90.77 81.4,90.76 81.4,90.2 v2(81.8,89.8)
  BOTTOM w0.121: R387.1 146.21,145.2 v1(146.58,144.83) 146.58,143.09 146.34,142.85 145.33,142.85 145.01,142.53 145.01,137.51 143.42,135.93 143.42,133.01 v1(143.36,132.94)
AM335X_USB1_VBUS: length 13.7
  TOP w0.254: U2.T18 v2(90.2,92.37) ; D10.1 90.4,101.19 v1(89.85,101.74)
  TOP w0.508: R564.2 90.28,102.95 90.08,102.75 90.08,101.97 v1(89.85,101.74)
  LY4 w0.508: v2(90.2,92.37) 90.51,92.37 91.27,93.13 91.27,95.87 90.66,96.48 90.66,100.93 v1(89.85,101.74)
AM335X_VDDA_ADC: length 42.7
  TOP w0.381: v2(80.2,83.4) U2.D8
  TOP w0.508: v1(76.82,82.08) 76.64,82.08 76.58,82.14 73.32,82.14 72.27,81.1 71.02,81.1 70.79,80.87 70.26,80.87 70.26,80.87 70.21,80.87 69.29,81.79 66.12,81.79 66.03,81.7 65.8,81.46 64.49,81.46 64.38,81.57 60.28,81.57 60.17,81.68 v1(59.54,81.68) ; v1(49.31,74.43) v1(59,74.43)
  BOTTOM w0.152: v1(76.82,82.08) 77.19,82.08 77.82,82.71 79.67,82.71 80.2,83.25 v2(80.2,83.4)
  BOTTOM w0.508: R501.1 v1(49.31,74.43) 49.6,74.71 50.33,74.71 ; v1(59,74.43) 59.54,74.97 59.54,79.68 59.52,79.7 59.52,81.66 v1(59.54,81.68)
AM335X_VDDS: length 40.2
  TOP w0.305: v2(81,81.8) U2.E6
  TOP w0.381: v2(89,89) U2.P14 ; v2(85.8,88.2) U2.K13 ; v2(88.2,81.8) U2.N6 ; v2(82.6,84.2) U2.F9 ; v2(89,84.2) U2.P9 ; U2.E14 v2(81,89)
  TOP w0.635: v1(99.99,111.54) 99.1,111.54 97.69,110.14 94.44,110.14 93.18,108.88 v1(88.21,108.88)
  LY4 w0.635: v1(88.21,108.88) 88.21,99.66 87.83,99.29 v1(87.83,98.59)
  BOTTOM w0.102: 81.42,90.21 81.42,89.68 81,89.26 v2(81,89) ; 81.42,90.21 81.42,91.07 C96.1 82.21,91.1 82.21,90.33 82.08,90.21 81.42,90.21
  BOTTOM w0.508: C50.1 92.43,89.68 92.71,89.95 92.77,89.95 v1(92.9,90.08) 92.45,90.52 C48.1
  BOTTOM w0.635: C249.1 99.99,110.43 v1(99.99,111.54) 100.37,111.92 100.37,112.56 C89.1 100.75,115.32 R498.1
AM335X_VDDS_DDR: length 65.6
  TOP w0.381: U2.F5 v2(81.8,81) U2.E5 ; U2.H5 v2(84.2,81) U2.J5 ; v2(82.6,81) U2.G5 ; U2.L5 v2(85.8,81) U2.K5
  TOP w0.635: R508.2 115.7,69.44 116.29,68.85 116.29,65.75 115.6,65.06 110.9,65.06 108.24,67.71 C233.1 105.36,67.71 104.37,68.7 104.37,70.33 101.57,73.13 v1(97.62,73.13) v1(97.04,73.13) v1(96.43,73.13)
  LY3 w0.635: v1(97.62,73.13) v1(97.04,73.13) v1(96.43,73.13) 95.3,74.26 v1(86.14,74.26)
  LY4 w0.635: 92.34,82.38 92.65,82.08 93.54,82.08 94.02,81.6 94.02,80.56 94.53,80.05 94.53,77.76 96.43,75.86 v1(96.43,73.13) v1(97.04,73.13) v1(97.62,73.13)
  BOTTOM w0.381: C76.1 83.3,81.7 v2(82.6,81) ; C309.1 85.69,73.8 v1(86.14,74.26) ; v2(85.8,81) 85.86,80.94 C78.1 ; v1(96.43,73.13) 96.31,73 95.61,73 C80.1 ; v2(84.2,81) 84.26,80.94 C79.1 ; C77.1 81.76,81.04 v2(81.8,81) ; C82.1 v1(97.62,73.13)
  BOTTOM w0.635: v1(97.62,73.13) v1(97.04,73.13) v1(96.43,73.13)
AM335X_VDDSHV1: length 54
  TOP w0.381: U2.P8 v2(89,83.4) U2.P7
  LY3 w0.102: 91.74,82.52 91.43,82.21 89.45,82.21 89,82.65 v2(89,83.4) 89.26,83.4 89.64,83.02 89.65,83.02 89.69,82.98 91.29,82.98
  LY3 w0.508: 91.29,82.98 92.06,82.21 95.67,82.21 98.34,79.54 99.16,79.54 99.8,80.17 v1(99.99,80.17) 100.62,80.81 100.62,81.95 101.38,82.71 v1(102.91,82.71) 103.54,83.35 107.1,83.35 v1(108.37,82.08)
  BOTTOM w0.381: v2(89,83.4) 88.31,83.4 C31.1
  BOTTOM w0.508: v1(102.91,82.71) 103.8,82.71 C32.1 ; C258.1 101.65,79.4 101.38,79.67 100.49,79.67 v1(99.99,80.17) ; v1(108.37,82.08) 115.48,74.97 120.69,74.97 122.11,73.54 R493.1
AM335X_VDDSHV2: length 39.3
  TOP w0.381: U2.P10 88.6,85.46 88.72,85.58 88.72,86.02 88.6,86.14 U2.P11 v2(89,86.6)
  TOP w0.508: C259.1 97.89,86.7 v1(95.85,86.7) 95.85,87.59 C92.1
  LY3 w0.635: v1(115.42,95.03) 110.5,95.03 108.29,92.82 102.4,92.82 101.12,91.54 101.12,89.74 99.11,87.73 96.87,87.73 v1(95.85,86.7) 95.07,86.7 94.73,87.04 93.69,87.04 93,86.35 92.54,86.35 91.99,85.8 89.68,85.8 89.15,86.33 89.15,86.45 v2(89,86.6)
  BOTTOM w0.381: v2(89,86.6) 89,85.95 C90.1
  BOTTOM w0.635: R545.1 114.43,95.03 v1(115.42,95.03)
AM335X_VDDSHV3: length 100.9
  TOP w0.381: U2.P12 v2(89,87.4) ; v2(89,88.2) U2.P13
  TOP w0.635: R546.1 v1(135,140.59)
  LY3 w0.635: 93.17,87.97 93.24,87.97 93.28,87.92 94.97,87.92 v1(95.99,88.94) 96.14,89.09 96.57,89.09 97.14,89.66 97.14,90.99 97.94,91.79 99.54,91.79 100.37,92.62 100.9,92.62 101.87,93.59 v1(102.31,93.59) 102.54,93.81 107.65,93.81 v1(108.85,95.01) ; v1(110.65,135.93) 119.29,135.93 119.29,137.96 123.61,142.28 124.78,142.28 125.03,142.53 125.61,142.53 126.02,142.12 126.02,142.02 126.28,141.77 126.28,141.26 126.78,140.75 128.43,140.75 129.83,142.15 133.45,142.15 v1(135,140.59)
  LY4 w0.635: v1(110.65,135.93) 109.89,135.17 109.89,105.57 111.54,103.92 111.54,101.15 110.55,100.16 110.55,96.71 v1(108.85,95.01)
  BOTTOM w0.381: v2(89,87.4) v2(89,88.2) 88.28,88.2 C94.1
  BOTTOM w0.508: C273.1 102.85,93.59 v1(102.31,93.59) ; C93.1 97.19,89.29 96.84,88.94 95.99,88.94 v1(95.99,88.94)
AM335X_VDDSHV4: length 104.9
  TOP w0.381: U2.H14 v2(84.2,89) U2.J14
  TOP w0.635: v1(122.47,133.7) 130.47,133.7 131.1,133.07 v1(133.58,133.07)
  LY3 w0.635: v1(84.16,114.59) 84.38,114.81 84.9,114.81 84.93,114.78 116.24,114.78 v1(119.42,111.61)
  LY4 w0.635: v1(84.15,95.39) 84.15,95.34 84.39,95.1 85.01,95.1 86.14,93.97 86.14,92.32 84.92,91.1 84.92,89.39 84.53,89 v2(84.2,89)
  BOTTOM w0.635: v1(119.42,111.61) 119.73,111.92 119.73,129.64 122.47,132.37 v1(122.47,133.7) ; R494.1 134.69,133.07 v1(133.58,133.07) ; v2(84.2,89) 84.07,89.13 C42.1 ; C43.1 83.6,94.58 84.15,95.12 v1(84.15,95.39) 84.15,95.83 84.82,96.51 C274.1 84.01,97.51 83.92,97.51 83.58,97.86 83.58,98.41 83.17,98.82 83.17,113.6 v1(84.16,114.59)
AM335X_VDDSHV5: length 74.6
  TOP w0.381: U2.K14 v2(85.8,89) U2.L14
  TOP w0.635: v1(91.24,130.57) 91.33,130.47 96.04,130.47 96.43,130.09 v1(98.34,130.09)
  LY4 w0.102: v2(85.8,89) 85.8,89.03 85.42,89.41 85.42,90.82 85.74,91.13 86.18,91.13 86.18,89.38 v2(85.8,89) ; v2(85.8,89) 86.71,89 86.98,89.27 86.98,90.76 86.97,90.77 86.97,91.48
  LY4 w0.508: v1(88.81,96.25) 88.81,95.16 88.68,95.03 88.68,93.19 86.97,91.48 86.52,91.48 86.18,91.13
  BOTTOM w0.635: v2(85.8,89) 85.94,89.14 C46.1 ; v1(88.81,96.25) 89.06,96.51 C45.1 89.06,97.45 90.14,98.53 90.14,100.24 90.59,100.68 90.59,102.8 C257.1 90.42,103.05 91.79,104.42 91.79,107.19 90.59,108.39 90.59,113.54 91.95,114.9 91.95,119.75 90.92,120.78 90.92,130.16 91.24,130.48 v1(91.24,130.57) ; R495.1 99.35,141.26 98.72,140.63 98.72,132.9 98.65,132.84 98.65,130.4 v1(98.34,130.09)
AM335X_VDDSHV6: length 15.7
  TOP w0.381: U2.G14 v2(82.6,89) U2.F14 ; U2.E10 v2(81,85.8) U2.E11 v2(81,86.6) U2.E12 ; U2.N5 v2(88.2,81) U2.P5 ; U2.P5 v2(89,81.8) U2.P6 ; U2.P5 v2(89,81) ; U2.E13 v2(81,88.2)
  TOP w0.635: C28.1 50.33,85.05 v1(50.31,85.07)
  BOTTOM w0.381: 70.9,83.48 70.14,83.48 v1(69.76,83.1) ; v2(78.52,92.24) 79.03,91.73 C47.1
  BOTTOM w0.635: v2(92.91,79.51) 93.1,79.51 93.31,79.29 93.69,79.29 C29.1 ; C25.1 92.24,81.69 92.37,81.57 v2(92.37,81.37) ; R496.1 50.31,86.85 v1(50.31,85.07) 51.51,85.07 C247.1 ; v2(82.6,89) 82.47,89.13 C27.1
AM335X_XDMA_EVENT_INTR0: length 16.1
  TOP w0.102: U2.A15 77.45,89.4 77.1,89.75
  TOP w0.121: 77.1,89.75 76.94,89.91 76.06,89.91 75.08,90.89 74.56,90.89 74.36,91.08 v1(73.92,91.08) ; R349.1 67.09,95.03 TP31.1 68.49,95.86 68.62,95.98 68.99,95.98 69.15,95.82 70.27,95.82 v1(71.03,95.06)
  BOTTOM w0.121: v1(73.92,91.08) 73.89,91.08 73.5,91.47 73.5,91.93 73.24,92.19 71.81,92.19 71.24,92.76 71.24,93.35 71.03,93.56 v1(71.03,95.06)
AM335X_XDMA_EVENT_INTR1: length 32.3
  TOP w0.102: v2(80.2,89) U2.D14
  TOP w0.121: R315.2 63.73,92.3 v1(63.66,92.3) 63.09,92.87 TP32.1
  LY3 w0.133: v1(63.54,95.8) 64.55,96.81 74.71,96.81 v1(75.98,98.08)
  BOTTOM w0.102: 77.51,92.9 77.51,91.1 77.89,90.72 77.89,90.21 78.14,89.95 78.9,89.95 79.16,90.21 79.51,90.21 79.52,90.22 79.78,89.96 79.78,89.58 80.2,89.16 v2(80.2,89)
  BOTTOM w0.121: R351.1 63.66,95.92 v1(63.54,95.8) 63.54,92.43 v1(63.66,92.3) ; 77.51,92.9 77.51,94.91 76.49,95.92 76.49,97.57 v1(75.98,98.08)
CAP_VBB_MPU: length 4.2
  TOP w0.102: v2(79.41,85.8) 79.41,85.79 U2.C10
  BOTTOM w0.102: 77.22,85.8 v2(79.41,85.8)
  BOTTOM w0.121: 77.22,85.8 77.09,85.8 76.62,86.27 C72.1
CAP_VDD_SRAM_CORE: length 12.6
  TOP w0.102: v2(80.2,85) U2.D9
  TOP w0.121: v1(76.59,85.42) 76.59,85.92 75.6,86.91 74.74,86.91 74.55,87.1 72.02,87.1 71.58,86.66 70.01,86.66 C60.1
  BOTTOM w0.102: v2(80.2,85) 79.94,85 79.56,85.38 78.74,85.38 78.56,85.2 77.73,85.2
  BOTTOM w0.121: v1(76.59,85.42) 77.52,85.42 77.73,85.2
CAP_VDD_SRAM_MPU: length 5.7
  TOP w0.102: v2(80.2,86.6) U2.D11
  BOTTOM w0.102: 77.63,87.42 78.26,86.79 80.01,86.79 v2(80.2,86.6)
  BOTTOM w0.121: 77.63,87.42 75.85,87.42 C71.1
COM_AUD_CLK: length 2.8
  TOP w0.121: J11.52 4.86,125.64 v1(4.61,125.39)
  BOTTOM w0.121: v1(4.61,125.39) 5.12,124.88 R338.2
COM_AUD_FSYNC: length 2.6
  TOP w0.121: J11.54 v1(4.61,126.28)
  BOTTOM w0.121: v1(4.61,126.28) 5.37,126.28 R339.2
COM_AUD_IN: length 2.6
  TOP w0.121: v1(4.61,127.04) 4.74,126.91 J11.56
  BOTTOM w0.121: v1(4.61,127.04) 5.5,127.04 R340.2
COM_AUD_OUT: length 2.8
  TOP w0.121: J11.58 4.86,127.55 v1(4.61,127.8)
  BOTTOM w0.121: v1(4.61,127.8) 5.12,127.8 R341.2
COM_BTRST: length 6.8
  TOP w0.121: v1(19.21,139.1) 17.44,140.88 J11.89
  BOTTOM w0.121: 20.1,139.1 v1(19.21,139.1)
COM_BTUARTCTS: length 2.8
  TOP w0.121: J11.70 4.86,134.53 v1(4.61,134.78)
  BOTTOM w0.121: R344.2 5.63,134.78 v1(4.61,134.78)
COM_BTUARTDEBUG: length 3
  TOP w0.121: 6.07,136.44 v1(4.61,136.44)
  BOTTOM w0.121: v1(4.61,136.44) 4.48,136.44 TP45.1
COM_BTUARTRTS: length 3
  TOP w0.121: J11.72 5.94,135.29 4.86,135.29 v1(4.61,135.55)
  BOTTOM w0.121: v1(4.61,135.55) 5.24,135.55 R345.2
COM_BTUARTRX: length 2.8
  TOP w0.121: 6.07,133.9 4.74,133.9 v1(4.61,134.02)
  BOTTOM w0.121: v1(4.61,134.02) 5.5,134.02 R343.2
COM_BTUARTTX: length 2.9
  TOP w0.121: v1(4.61,133.13) 4.74,133.26 J11.66
  BOTTOM w0.121: R342.2 5.24,133.13 v1(4.61,133.13)
COM_GNSS_PPS_OUT: length 21.8
  TOP w0.121: U14.10 19.89,126.38 19.35,126.92 19.35,127.67 16.45,130.56 8.92,130.56 8.32,129.96 v1(7.66,129.96) ; J11.50 6.2,125.13 7.28,125.13 7.72,125.57 v1(7.72,126.15)
  BOTTOM w0.121: v1(7.72,126.15) 8.1,126.53 8.1,129.52 v1(7.66,129.96)
COM_GNSS_TIME_STAMP: length 25.9
  TOP w0.121: U13.10 19.11,120.03 18.71,120.43 18.71,123.61 17.94,124.37 17.94,127.42 15.79,129.57 10.06,129.57 8.79,128.29 8.79,125.38 7.77,124.37 J11.48
COM_SDIO_CLK: length 6.2
  TOP w0.121: J11.20 7.4,115.48 v1(7.66,115.23)
  BOTTOM w0.121: v1(7.66,115.23) 7.66,113.32 R334.1 R485.2
COM_SDIO_CMD: length 5.1
  TOP w0.121: J11.24 7.28,116.75 v1(7.66,116.37)
  BOTTOM w0.121: R486.2 R333.1 6.64,115.02 7.15,115.52 7.15,115.86 v1(7.66,116.37)
COM_SDIO_D0: length 6.2
  TOP w0.121: J11.26 v1(7.66,117.39)
  BOTTOM w0.121: R487.2 R332.1 7.83,116.88 8.14,116.57 8.34,116.57 8.47,116.7 8.47,117.26 8.34,117.39 v1(7.66,117.39)
COM_SDIO_D1: length 5.3
  TOP w0.121: v1(8.42,118.02) J11.28
  BOTTOM w0.121: v1(8.42,118.02) 8.39,117.99 6.67,117.99 R331.1 R488.2
COM_SDIO_D2: length 7.1
  TOP w0.121: 6.07,118.66 v1(7.66,118.66)
  BOTTOM w0.121: R330.1 R489.2 7.23,119.72 7.23,119.47 7.36,119.35 8.2,119.35 8.31,119.46 8.6,119.46 8.72,119.33 8.72,118.81 8.6,118.68 7.68,118.68 v1(7.66,118.66)
COM_SDIO_D3: length 6.4
  TOP w0.121: v1(7.86,119.85) 7.3,119.29 J11.32
  BOTTOM w0.121: R329.1 R490.2 7.89,121.35 7.89,119.87 v1(7.86,119.85)
COM_SLOW_CLK: length 36.3
  TOP w0.121: v1(15.91,109.43) 15.51,109.43 15.18,109.77 J11.1 ; v1(15.91,137.96) 16.1,137.78 U15.12
  BOTTOM w0.121: v1(15.91,109.43) 17.24,110.77 17.24,136.52 16.35,137.41 16.33,137.41 16.22,137.52 16.22,137.65 v1(15.91,137.96)
COM_WL_IRQ: length 8.2
  TOP w0.121: J11.34 6.07,119.94 6.16,120.03 7.36,120.03 7.64,120.31 11.21,120.31 v1(12.48,119.04)
  BOTTOM w0.121: R337.2 v1(12.48,119.04)
COM_WL_RS232_RX: length 3.1
  TOP w0.121: 14.07,113.58 v1(12.23,113.58)
  BOTTOM w0.121: v1(12.23,113.58) TP43.1
COM_WL_RS232_TX: length 2.8
  TOP w0.121: J11.11 15.4,112.94 v1(15.66,112.69)
  BOTTOM w0.121: TP42.1 15.4,112.94 v1(15.66,112.69)
COM_WL_RST: length 3.1
  TOP w0.121: J11.4 4.48,110.4 v1(4.36,110.27)
  BOTTOM w0.121: v1(4.36,110.27) 4.61,110.02 R327.2
COM_WL_UART_DBG: length 2.5
  TOP w0.121: J11.15 v1(15.66,114.21)
  BOTTOM w0.121: v1(15.66,114.21) TP44.1
COMAUD_CLK: length 21.2
  TOP w0.121: U14.13 19.03,124.43 18.33,125.13 18.33,127.64 16.15,129.82 9.8,129.82 8.54,128.55 8.54,125.76 v1(7.66,124.88)
  BOTTOM w0.121: R338.1 v1(7.66,124.88)
COMAUD_FSYNC: length 26.3
  TOP w0.121: v1(8.78,124.75) 9.03,125.01 9.03,128.03 10.32,129.32 15.69,129.32 17.31,127.7 17.31,120.56 18.49,119.38 U13.11
  BOTTOM w0.121: v1(8.78,124.75) 8.78,124.77 8.23,125.32 7.34,125.32 R339.1
COMAUD_IN: length 19
  TOP w0.121: U14.12 19.4,125.08 18.71,125.77 18.71,127.61 16.25,130.06 9.54,130.06 8.29,128.82 8.29,127.67 v1(7.66,127.04)
  BOTTOM w0.121: R340.1 7.53,127.16 v1(7.66,127.04)
COMAUD_OUT: length 17.4
  TOP w0.121: v1(7.66,128.94) 9.03,130.31 16.35,130.31 18.96,127.7 18.96,126.28 19.51,125.73 U14.11
  BOTTOM w0.121: v1(7.66,128.94) 7.02,128.31 R341.1
COMBTRST: length 2.2
  TOP w0.121: v1(21.88,139.1) 21.65,139.08 U15.10
  BOTTOM w0.121: R353.2 v1(21.88,139.1)
COMBTUARTCTS: length 16.4
  TOP w0.121: U16.12 19.16,131.43 18.89,131.69 8.56,131.69 7.97,132.28 7.97,134.47 v1(7.53,134.91)
  BOTTOM w0.121: R344.1 v1(7.53,134.91)
COMBTUARTRTS: length 16.6
  TOP w0.121: U16.10 16.65,132.73 16.11,132.18 11.4,132.18 10.96,132.63 10.96,134.4 9.31,136.05 v1(7.53,136.05)
  BOTTOM w0.121: R345.1 v1(7.53,136.05)
COMBTUARTRX: length 15.8
  TOP w0.121: v1(7.53,133.77) 7.53,132.37 8.46,131.44 18.42,131.44 19.09,130.78 U16.13
  BOTTOM w0.121: R343.1 v1(7.53,133.77)
COMBTUARTTX: length 14.1
  TOP w0.121: v1(8.41,132.63) 9.1,131.94 16.62,131.94 16.76,132.08 U16.11
  BOTTOM w0.121: R342.1 v1(8.41,132.63)
COMWL_IRQ: length 6.7
  TOP w0.121: v1(15.91,119.57) 17.24,119.57 18.73,118.08 U13.13
  BOTTOM w0.121: R337.1 15.38,119.04 v1(15.91,119.57)
COMWL_RST: length 37.1
  TOP w0.121: U15.13 17.21,137.13 v1(16.06,135.98)
  BOTTOM w0.121: R327.1 v1(7.66,110.4) 11.21,113.96 11.21,134.66 12.53,135.98 v1(16.06,135.98)
DDR_A0: length 61.3
  TOP w0.102: U2.F3 v2(81.8,79.4)
  TOP w0.121: v1(90.58,61.44) U33.K3 ; v1(75.98,61.44) U34.K3 ; R604.2 93.28,66.2 93.39,66.1 93.39,65.63 93.29,65.53 v1(92.85,65.53)
  LY4 w0.076: 87.29,61.21 87.4,61.21 87.53,61.08 90.22,61.08 v1(90.58,61.44) 90.58,62.29 90.99,62.7 90.99,63.21 91.22,63.44 91.55,63.44 91.78,63.67 91.78,64.46 ; v1(75.98,61.44) 76.41,61.87 76.41,62.39 76.82,62.8 77.18,62.8 77.51,63.13 79.06,63.13 79.92,63.99 80.3,63.99 80.4,63.89 80.4,63.59 80.53,63.46 84.26,63.46
  LY4 w0.133: 91.78,64.46 92,64.68 92,64.74 92.47,65.21 92.53,65.21 v1(92.85,65.53) ; 84.26,63.46 84.59,63.79 84.75,63.79 85.66,62.88 85.66,61.97 85.79,61.84 86.43,61.84 87.06,61.21 87.29,61.21
  BOTTOM w0.121: v1(75.98,61.44) 76.18,61.64 76.27,61.64 76.47,61.84 78.53,61.84 78.54,61.84 78.54,61.84 78.77,62.07 78.77,62.69 78.8,62.72 78.8,63.82 78.67,63.94 77.86,63.94 77.74,64.07 77.74,64.71 77.86,64.83 78.62,64.83 78.75,64.96 78.75,65.19 78.62,65.32 77.86,65.32 77.74,65.44 77.74,67.14 77.86,67.27 78.04,67.27 78.17,67.14 78.17,66.53 78.29,66.41 78.45,66.41 78.57,66.53 78.57,67.8 78.45,67.93 76.9,67.93 76.77,67.8 76.77,67.12 76.64,66.99 75.7,66.99 75.58,67.12 75.58,67.7 75.7,67.83 76.02,67.83 76.3,68.11 76.3,68.3 76.43,68.43 78.17,68.43 78.29,68.56 78.29,69.38 78.42,69.51 79.5,69.51 79.63,69.63 79.63,69.74 79.64,69.76 79.64,71.39 79.64,73.98 79.45,74.17 79.45,76.75 80.35,77.65 80.36,77.65 81.8,79.09 v2(81.8,79.4)
DDR_A1: length 60.9
  TOP w0.121: U2.H1 83.8,76.83 83.8,75.02 84.14,74.69 84.14,74.19 83.27,73.33 v1(83.27,72.88) ; v1(89.78,59.04) U33.L7 ; v1(75.18,59.04) U34.L7
  LY4 w0.076: v1(89.78,59.04) 89.41,58.67 87.69,58.67 87.54,58.81 87.32,58.81 87.31,58.83
  LY4 w0.133: v1(77.28,69.38) 80.78,72.88 v1(83.27,72.88) ; v1(75.18,59.04) 74.79,59.42 74.79,59.68 74.92,59.81 77.13,59.81 77.35,60.03 77.35,60.46 77.48,60.58 82.79,60.58 82.92,60.46 82.92,59.37 83.04,59.25 84.63,59.25 84.64,59.25 85.46,59.25 85.89,58.83 87.31,58.83
  BOTTOM w0.121: R605.2 86.52,57.54 87.62,58.63 89.38,58.63 v1(89.78,59.04)
  BOTTOM w0.127: v1(75.18,59.04) 75.18,59.75 74.08,60.84 72.58,60.84 72.45,60.97 72.45,62.17 72.33,62.29 70.85,62.29 69.75,63.4 69.75,64.97 70.16,65.38 71.08,65.38 71.21,65.25 71.21,65.04 71.33,64.91 72.36,64.91 72.46,65.01 72.46,66.69 72.81,67.05 74.15,67.05 74.48,67.38 74.48,68.55 74.9,68.98 74.9,68.98 75.5,69.58 77.08,69.58 v1(77.28,69.38)
DDR_A2: length 61
  TOP w0.102: U2.E4 v2(81,80.2)
  TOP w0.121: v1(75.18,61.44) U34.L3 ; v1(90.89,65.34) 91.2,65.65 91.2,65.84 R606.2 ; v1(89.78,62.24) U33.L3
  LY4 w0.076: 90.3,64.25 90.15,64.1 90.15,62.6 v1(89.78,62.24) 88.96,61.41 87.72,61.41 87.39,61.73 87.39,61.73 ; 79.72,64.46 78.73,63.47 77.41,63.47 77.05,63.11 76.33,63.11 75.61,62.39 75.61,61.87 v1(75.18,61.44)
  LY4 w0.127: 79.72,64.46 79.78,64.46
  LY4 w0.133: 79.78,64.46 79.79,64.46 79.84,64.51 84.84,64.51 86.28,63.07 86.28,62.76 87.31,61.73 87.39,61.73 ; v1(90.89,65.34) 90.89,66.25 90.77,66.38 90.43,66.38 90.3,66.25 90.3,64.25
  BOTTOM w0.121: v2(81,80.2) 81.39,79.81 81.39,79.24 81.34,79.19 81.34,79.06 79.2,76.91 79.2,76.47 79.07,76.34 78.68,76.34 78.55,76.21 78.55,75.93 78.68,75.81 79.07,75.81 79.2,75.68 79.2,75.48 79.07,75.35 78.68,75.35 78.55,75.22 78.55,74.99 78.68,74.87 79.03,74.87 79.16,74.74 79.16,74.51 79.03,74.38 78.68,74.38 78.55,74.26 78.55,74.08 78.88,73.75 79.26,73.75 79.39,73.62 79.39,71.16 79.26,71.03 78.53,71.03 78.19,70.7 78.19,70.47 78.32,70.34 79.25,70.34 79.37,70.22 79.37,69.94 79.25,69.81 78.17,69.81 78.04,69.68 78.04,68.81 77.91,68.68 76.8,68.68 76.67,68.81 76.67,68.95 76.54,69.07 76.16,69.07 76.05,68.96 76.05,68.21 75.92,68.08 75.45,68.08 75.32,67.96 75.32,66.81 75.45,66.69 77.35,66.69 77.48,66.56 77.48,66.23 77.35,66.1 76.47,66.1 76.34,65.98 76.34,65.7 76.49,65.54 77.28,65.54 77.41,65.42 77.41,65.27 77.28,65.14 77.02,65.14 76.9,65.01 76.9,64.93 76.9,64.53 76.37,64 76.37,62.4 76.37,62.4 76.37,62.07 76.14,61.84 75.83,61.84 75.42,61.44 v1(75.18,61.44)
DDR_A3: length 61.9
  TOP w0.102: v2(79.4,79.4) U2.C3
  TOP w0.121: v1(91.86,65.34) 91.86,64.88 91.99,64.76 92.21,64.76 92.34,64.88 92.34,65.72 R607.2 ; v1(75.98,62.24) U34.K2 75.91,63.1 75.91,63.57 75.65,63.83 75.65,64.58 75.14,65.09 74.1,65.09 72.02,67.17 72.02,69.02 72.8,69.8 73.11,69.8 v1(73.42,70.12) ; U33.K2 v1(90.58,63.04)
  LY4 w0.076: 79.87,64.25 78.94,63.31 77.47,63.31 77.11,62.95 76.69,62.95 v1(75.98,62.24) ; 87.29,61.47 87.35,61.47 87.6,61.23 89.3,61.23 90.31,62.24 90.31,62.76 v1(90.58,63.04) 90.95,63.4 90.95,64.05
  LY4 w0.133: 90.95,64.05 90.95,64.77 91.08,64.89 91.34,65.15 91.34,65.87 91.47,66 91.73,66 91.86,65.87 v1(91.86,65.34) ; 79.87,64.25 84.67,64.25 85.97,62.95 85.97,62.23 86.09,62.1 86.54,62.1 87.17,61.47 87.29,61.47
  BOTTOM w0.121: v2(79.4,79.4) 77.95,79.4 76.87,78.32 76.54,78.32 74.24,76.01 74.24,75.83 74.49,75.58 74.49,75.4 74.31,75.22 74.13,75.22 73.88,75.47 73.7,75.47 73.42,75.2 73.42,74.34 73.54,74.21 75.25,74.21 75.37,74.08 75.37,73.83 75.25,73.7 73.54,73.7 73.42,73.57 73.42,73.32 73.54,73.19 75.25,73.19 75.37,73.07 75.37,72.81 75.25,72.68 73.57,72.68 73.44,72.56 73.44,72.3 73.57,72.18 75.25,72.18 75.37,72.05 75.37,71.8 75.25,71.67 73.54,71.67 73.42,71.54 v1(73.42,70.12)
DDR_A4: length 60.9
  TOP w0.121: U2.C2 80.14,78.66 80.14,77.92 78.57,76.35 78.57,75.22 78.3,74.94 77.53,74.94 76.75,74.15 76.75,73.14 76.62,73.01 75.86,73.01 75.73,73.14 75.73,73.76 75.6,73.88 74.69,73.88 74.56,73.76 74.56,71.33 74.31,71.08 72.94,71.08 72.68,70.83 72.68,70.32 71.15,68.79 71.15,65.9 71.28,65.77 v1(71.73,65.77) ; U33.L8 v1(89.78,57.44) ; U34.L8 v1(75.18,57.44)
  LY4 w0.133: v1(75.18,57.44) 75.59,57.85 79.34,57.85 79.62,57.57 79.62,56.53 80.28,55.87 82.41,55.87 82.79,55.49 89.14,55.49 89.39,55.73 89.39,56.47 89.39,56.47 89.39,57.04 v1(89.78,57.44)
  BOTTOM w0.076: v1(89.78,57.44) 89.78,57.87 89.66,58 89.48,58 89.35,57.87 89.35,56.48 89.11,56.24 89.11,55.54
  BOTTOM w0.121: R608.2 91.5,54.88 91.32,54.88 90.93,55.27 89.38,55.27 89.11,55.54 ; v1(71.73,65.77) 71.13,65.77 70.99,65.63 70.05,65.63 69.5,65.07 69.5,63.29 72.22,60.57 73.95,60.57 74.77,59.75 74.77,58.87 74.61,58.72 74.61,58 v1(75.18,57.44)
DDR_A5: length 61.1
  TOP w0.121: R609.2 90.13,66.2 90.26,66.08 90.26,65.24 90.07,65.05 89.91,65.05 v1(89.6,65.37) ; U33.L2 v1(89.78,63.04) ; U34.L2 v1(75.18,62.24)
  TOP w0.127: U2.B1 79,77.97 78.69,77.65 78.67,77.65 78.27,77.25 74.78,77.25 74.32,76.8 73.92,76.8 73.71,76.59 73.71,75.65 73.59,75.53 72.45,75.53 72.33,75.4 72.33,75.09 72.45,74.97 73.59,74.97 73.71,74.84 73.71,74.54 73.59,74.41 72.5,74.41 72.3,74.21 72.3,72.35 72.05,72.1 69.84,72.1 69.71,71.97 69.71,70.73 69.58,70.6 69.18,70.6 69.05,70.73 69.05,71.94 68.92,72.07 68.59,72.07 68.46,71.94 68.46,66.66 v1(70.45,64.68)
  LY4 w0.076: v1(75.18,62.24) 76.2,63.26 76.99,63.26 77.37,63.64 78.61,63.64 79.65,64.67 ; 88.99,64.35 89.25,64.09 89.29,64.09 89.41,63.96 89.41,63.4 v1(89.78,63.04) 89.39,62.65 89.39,62.13 88.83,61.56 87.85,61.56 87.29,62.13
  LY4 w0.133: 87.29,62.13 86.61,62.8 86.61,63.14 84.99,64.77 79.74,64.77 79.65,64.67 ; 88.99,64.35 88.99,65.9 89.11,66.03 89.47,66.03 89.6,65.9 v1(89.6,65.37)
  BOTTOM w0.121: v1(70.45,64.68) 71.06,64.07 73.04,64.07 73.16,63.95 73.16,63.51 73.42,63.26 74.92,63.26 75.18,63 v1(75.18,62.24)
DDR_A6: length 61.1
  TOP w0.102: U2.D5 v2(80.2,81)
  TOP w0.121: v1(88.98,57.44) U33.M8 ; v1(74.38,57.44) U34.M8
  LY4 w0.133: v1(74.38,57.44) 74.66,57.71 74.66,57.89 74.88,58.12 79.6,58.12 79.89,57.83 79.89,56.68 80.4,56.17 82.54,56.17 82.94,55.76 88.42,55.76 88.58,55.92 88.58,57.03 v1(88.98,57.44)
  BOTTOM w0.076: 88.53,55.54 88.45,55.61 88.45,55.76 88.71,56.02 88.71,56.27 88.56,56.43 88.56,56.78 88.73,56.96 88.73,57.06 88.56,57.24 88.56,57.88 88.68,58 88.86,58 88.98,57.88 v1(88.98,57.44)
  BOTTOM w0.102: 80.61,80.5 80.61,79.95
  BOTTOM w0.121: 88.91,55.38 89.27,55.02 89.91,55.02 90.11,54.83 90.21,54.83 90.41,55.02 90.64,55.02 90.72,54.95 R610.2 ; v2(80.2,81) 80.61,80.59 80.61,80.5 ; v1(74.38,57.44) 73.97,57.84 73.97,59.28 73.64,59.62 71.34,59.62 68.9,62.06 68.9,63.04 68.91,63.05 68.91,63.42 68.9,63.43 68.9,65.39 70.42,66.92 70.65,66.92 71.68,67.94 73.47,67.94 75.46,69.93 76.61,69.93 78.88,72.2 78.88,72.98 78.02,73.85 78.02,76.52 80.43,78.93 80.43,79.03 80.61,79.21 80.61,79.95
  BOTTOM w0.127: 88.53,55.54 88.68,55.38 88.91,55.38
DDR_A7: length 61.1
  TOP w0.121: v1(74.38,62.24) U34.M2 ; v1(81.44,68.46) 81.44,71 81.32,71.13 78.02,71.13 77.89,71.26 77.89,71.84 78.02,71.97 79.41,71.97 81.44,74 81.44,74.97 81.85,75.37 81.85,77.76 81.78,77.83 81.78,78.63 81.41,79 U2.E2 ; v1(88.98,63.04) U33.M2
  LY4 w0.076: 87.31,63.24 87.64,62.91 87.64,62.41 87.81,62.24 87.81,62.08 88.03,61.87 88.33,61.87 88.55,62.08 88.55,62.6 v1(88.98,63.04) ; 77.25,64.2 76.57,64.2 76.26,63.89 76.03,63.89 v1(74.38,62.24) 74.12,61.97 74.12,61.7 73.95,61.52 73.95,60.94 73.85,60.84 73.21,60.84 72.81,61.25
  LY4 w0.127: v1(81.44,68.46) 81.44,68.91 81.35,69.01 79.3,69.01 78.09,67.8 77.02,67.8 76.38,67.16 74.88,67.16 74.56,66.84 74.56,65.8
  LY4 w0.133: 74.56,65.8 74.07,65.32 72.99,65.32 72.66,64.98 72.66,61.4 72.81,61.25 ; 87.31,63.24 85.24,65.3 79.5,65.3 78.4,64.2 77.25,64.2
  BOTTOM w0.076: 90.49,64.68 90.49,64.43 90.21,64.15 90.21,61.99 90.09,61.86 89.57,61.86 89.35,62.08 89.35,62.67 v1(88.98,63.04)
  BOTTOM w0.121: R611.2 90.18,65.85 90.18,65.33 90.49,65.03 90.49,64.68
DDR_A8: length 59.1
  TOP w0.102: v1(80.2,80.2) U2.D4
  TOP w0.121: v1(88.18,57.44) 87.74,57.44 87.62,57.56 87.62,58.05 87.74,58.18 88.51,58.18 88.58,58.1 U33.N8 ; v1(73.58,57.44) U34.N8
  LY4 w0.133: v1(88.18,57.44) 86.94,56.2 83.06,56.2 83.02,56.24 83.01,56.24 82.78,56.47 82.78,56.48 82.77,56.48 82.77,56.8 82.76,56.81 82.76,56.82 82.54,57.04 81.06,57.04 79.72,58.38 74.51,58.38 73.86,57.73 73.86,57.71 v1(73.58,57.44)
  BOTTOM w0.076: 87.98,55.6 87.98,55.69 88.11,55.82 88.15,55.82 88.28,55.94 88.28,56.12 88.15,56.25 87.94,56.25 87.81,56.37 87.81,56.79 87.82,56.79 87.82,56.88 87.95,57 88.12,57 88.18,57.07 v1(88.18,57.44)
  BOTTOM w0.121: 88.05,55.54 88.48,55.1 88.81,55.1 89.19,54.73 89.19,54.7 89.37,54.52 R612.2 ; v1(73.58,57.44) 71.49,57.44 67.58,61.35 67.58,65.8 69.66,67.88 70.09,67.88 70.92,68.71 73.16,68.71 73.87,69.42 73.87,70.95 74.34,71.41 75.35,71.41 75.63,71.69 75.63,73.42 77.38,75.17 77.38,77.43 78.96,79.01 79.62,79.01 79.81,79.2 79.81,79.81 v1(80.2,80.2)
  BOTTOM w0.127: 87.98,55.6 88.05,55.54
DDR_A9: length 60.9
  TOP w0.121: v1(88.45,65.47) 88.14,65.78 87.95,65.78 87.82,65.91 87.82,66.43 87.95,66.56 88.45,66.56 R613.2 ; U34.M3 v1(74.38,61.44) 73.86,60.92 73.42,60.92 72.81,61.53 72.81,63.03 68.9,66.94 68.9,70.12 69.02,70.24 69.39,70.24 69.52,70.12 69.52,68.08 69.65,67.96 70.29,67.96 70.42,68.08 70.42,70.45 70.54,70.57 70.94,70.57 70.95,70.57 71.13,70.57 71.26,70.7 71.26,71.46 71.39,71.59 72.68,71.59 72.94,71.84 72.94,73.65 73.19,73.9 73.8,73.9 74.22,74.32 74.22,75.41 74.41,75.6 74.68,75.6 74.87,75.41 74.87,74.54 74.99,74.41 76.59,74.41 77.79,75.6 77.79,75.92 79.8,77.93 U2.C1 ; v1(88.98,62.24) U33.M3
  LY4 w0.076: 79.15,64.55 78.4,63.79 77.25,63.79 76.93,63.47 76.93,63.47 76.9,63.44 75.81,63.44 74.76,62.39 74.76,61.82 v1(74.38,61.44) ; 87.39,62.39 87.55,62.23 87.55,62.13 87.97,61.71 88.46,61.71 v1(88.98,62.24) 88.98,62.51 89.35,62.88 89.35,63.23 89.11,63.47 88.7,63.47 88.58,63.59
  LY4 w0.133: 79.15,64.55 79.63,65.03 85.1,65.03 87.39,62.74 87.39,62.39 ; 88.58,63.59 88.58,63.96 88.58,63.96 88.58,64 88.53,64.05 88.53,64.45 88.57,64.49 88.57,64.87 88.45,64.98 v1(88.45,65.47)
